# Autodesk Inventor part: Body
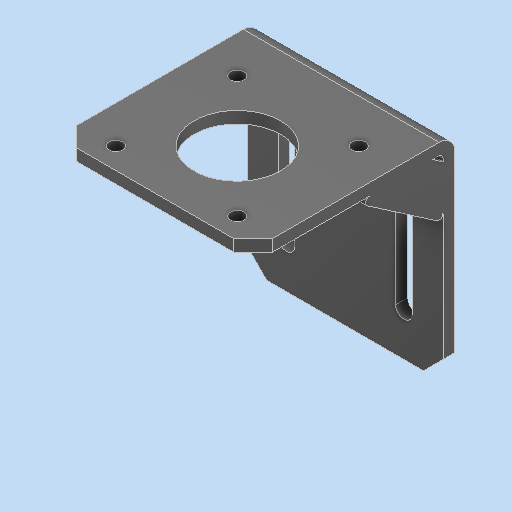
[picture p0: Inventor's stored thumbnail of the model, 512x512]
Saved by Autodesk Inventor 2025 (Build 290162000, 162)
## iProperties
Created: 2024-10
Part Number: Body
Material: Generico
Description: FreeCAD Model
Document SubType Name: Modeling
Designer: R5800u
Authority: Unknown
Density: 1 g/cm^3
Appearance: Default
Title: Open CASCADE Shape Model
Sending System: FreeCAD
Preprocessor: Open CASCADE STEP processor 7.6
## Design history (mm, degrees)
feature "Base1"
node "Solido1"
